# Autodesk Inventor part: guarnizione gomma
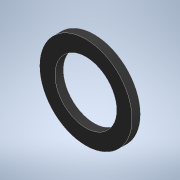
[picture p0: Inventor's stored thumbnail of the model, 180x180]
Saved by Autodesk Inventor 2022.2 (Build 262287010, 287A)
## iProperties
Created: 2022-03
Part Number: guarnizione gomma
Material: Gomma
Document SubType Name: Modeling
Designer: 18619647
Density: 0.93 g/cm^3
Appearance: Gomma - Nero
Author: 18619647
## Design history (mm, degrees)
sketch "Schizzo1"
  geometry: C1 r 8.25 at (0, 0); C2 r 5.5 at (0, 0); 1 further point
  constraints: 2 centre point, 2 coincident
  dimensions: "d0" = 16.5 diameter of C1; "d1" = 11 diameter of C2
extrude "Estrusione1" new body sketch "Schizzo1" distance "d2" = 1.5; taper "d3" = 0 deg
node "Solido1"
